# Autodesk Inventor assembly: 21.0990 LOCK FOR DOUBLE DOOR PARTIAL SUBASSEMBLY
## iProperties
Created: 2007-03
Part Number: 21.0990 LOCK FOR DOUBLE DOOR PARTIAL SUBASSEMBLY
Document SubType Name: Assembly
Designer: Andy Moles
Author: Andy Moles
